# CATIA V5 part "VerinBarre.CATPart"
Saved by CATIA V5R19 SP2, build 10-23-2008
Part number: VerinBarre
Bounding box of the stored display mesh (mm): x -19.255 to 25.726, y 11.213 to 91.213, z 156.233 to 186.194
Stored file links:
  D:\France\IFMA\IAO\Projet\VerinBarre.CATPart
  D:\France\IFMA\IAO\Projet\pruangdaja_CAO.CATProduct
  D:\France\IFMA\IAO\Projet\SqueletteVerrinBarre.CATPart
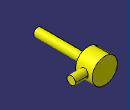
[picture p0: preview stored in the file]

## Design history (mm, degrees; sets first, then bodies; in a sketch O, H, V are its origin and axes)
Body1 (main body)
Body2
  Solid1: linked copy from another document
